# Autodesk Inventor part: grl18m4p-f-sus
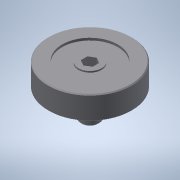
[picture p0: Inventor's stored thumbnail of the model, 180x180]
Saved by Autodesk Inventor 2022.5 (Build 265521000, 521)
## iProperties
Created: 2016-12
Part Number: grl18m4p-f-sus
Material: 一般
Document SubType Name: Modeling
Designer: imaocorp
Density: 1 g/cm^3
Appearance: 既定
Author: imaocorp
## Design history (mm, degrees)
node "grl18m4p-f-sus.x_t1"
node "grl18m4p-f-sus"
node "Base1"
